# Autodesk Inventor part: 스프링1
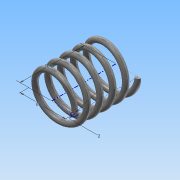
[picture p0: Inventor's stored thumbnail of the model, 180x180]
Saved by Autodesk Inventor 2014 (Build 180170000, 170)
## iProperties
Created: 2016-01
Part Number: 스프링1
Material: 강철, 탄소
Document SubType Name: Modeling
Designer: Administrator
Mass: 6.44159 g
Surface Area: 16.7002 cm^2
Volume: 0.818499 cm^3
Density: 7.87 g/cm^3
Appearance: 반연마
Author: Administrator
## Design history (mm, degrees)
sketch "스케치1"
  geometry: L1 (0, 0)-(8.5, 0); L2 (8.5, 0)-(8.5, 17.5); L3 (8.5, 17.5)-(0, 17.5); L4 (0, 17.5)-(0, 0); C1 r 1 at (8.5, 0)
  constraints: 8 end point, 2 parallel, 1 centre point, 1 coincident, 1 horizontal, 1 perpendicular
  dimensions: "d0" = 2 diameter of C1; "d1" = 17 diameter of L2 L4; "d2" = 17.5 distance of L3.end L1.start (derived)
feature "코일1" sketch "스케치1" pitch "d3" = 10; turns "d5" = 5; dims "d4" = 17.5 (= d2), "d6" = 0, angle "d7" = 90 deg, angle "d8" = 90 deg, "d9" = 0, "d10" = 0
node "작업 평면1"
sketch "스케치2"
  geometry: L1 (-9.5, 0)-(-7.5, 0) reference; 1 further point
  constraints: 1 horizontal alignment
extrude "돌출1" cut sketch "스케치2" distance "d12" = 10; taper "d13" = 0 deg
node "작업 평면2"
sketch "스케치3"
  geometry: L1 (-7.5, 0)-(-9.5, 0) reference; 1 further point
  constraints: 1 horizontal alignment
extrude "돌출2" cut sketch "스케치3" distance "d15" = 10; taper "d16" = 0 deg
node "솔리드1"
node "절단 모서리 투영1"
node "절단 모서리 투영2"
other parameters: "d11" = 17.5 (= d2), "d14" = 0
